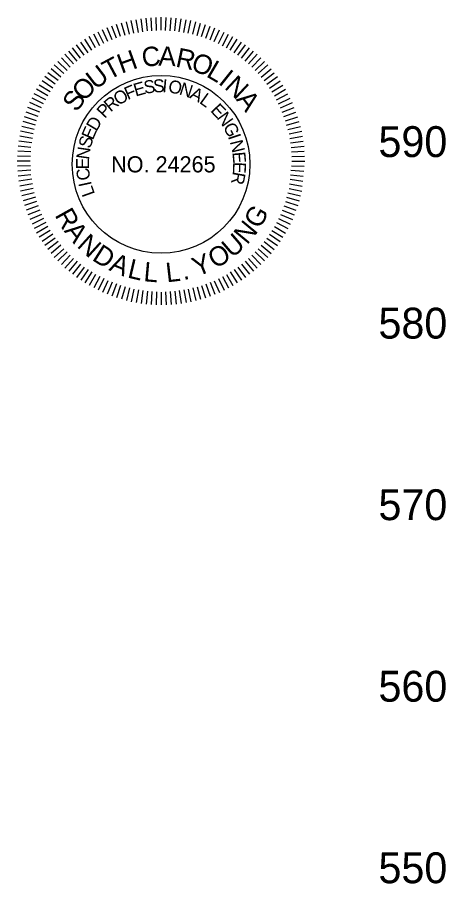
# Model space of a CAD drawing. Extents: x 1964377 to 1966966, y 1116414 to 1123213.
# Drawn here: x 1966831.8 to 1966949.9, y 1116676.7 to 1116915.3 of the extents above; entities that cross this region are included whole.
import ezdxf

# ---------------------------------------------------------------- set-up
doc = ezdxf.new("R2010")
doc.units = 0
doc.layers.add('RD_DDB_Profile_Elev', color=7, linetype='Continuous')
doc.layers.add('RD_TX_PEShield', color=7, linetype='Continuous')

msp = doc.modelspace()

# ---------------------------------------------------------------- linework, layer by layer
at = {"layer": 'RD_TX_PEShield'}
for p, q in [((1966861.52, 1116910.28), (1966860.54, 1116913.7)), ((1966861.52, 1116910.28), (1966860.54, 1116913.7)), ((1966862.74, 1116910.61), (1966861.88, 1116914.06)), ((1966862.74, 1116910.61), (1966861.88, 1116914.06)), ((1966863.95, 1116910.93), (1966863.21, 1116914.41)), ((1966863.95, 1116910.93), (1966863.21, 1116914.41)), ((1966865.2, 1116911.13), (1966864.58, 1116914.63)), ((1966865.2, 1116911.13), (1966864.58, 1116914.63)), ((1966866.44, 1116911.33), (1966865.94, 1116914.85)), ((1966866.44, 1116911.33), (1966865.94, 1116914.85)), ((1966867.68, 1116911.52), (1966867.31, 1116915.06)), ((1966867.68, 1116911.52), (1966867.31, 1116915.06)), ((1966868.94, 1116911.59), (1966868.69, 1116915.14)), ((1966868.94, 1116911.59), (1966868.69, 1116915.14)), ((1966870.19, 1116911.65), (1966870.07, 1116915.21)), ((1966870.19, 1116911.65), (1966870.07, 1116915.21)), ((1966871.45, 1116911.72), (1966871.45, 1116915.28)), ((1966871.45, 1116911.72), (1966871.45, 1116915.28)), ((1966872.7, 1116911.65), (1966872.83, 1116915.21)), ((1966872.7, 1116911.65), (1966872.83, 1116915.21)), ((1966873.96, 1116911.59), (1966874.21, 1116915.14)), ((1966873.96, 1116911.59), (1966874.21, 1116915.14)), ((1966875.21, 1116911.52), (1966875.59, 1116915.06)), ((1966875.21, 1116911.52), (1966875.59, 1116915.06)), ((1966876.46, 1116911.33), (1966876.95, 1116914.85)), ((1966876.46, 1116911.33), (1966876.95, 1116914.85)), ((1966877.7, 1116911.13), (1966878.32, 1116914.63)), ((1966877.7, 1116911.13), (1966878.32, 1116914.63)), ((1966878.94, 1116910.93), (1966879.68, 1116914.41)), ((1966878.94, 1116910.93), (1966879.68, 1116914.41)), ((1966878.94, 1116910.93), (1966879.68, 1116914.41)), ((1966880.16, 1116910.61), (1966881.02, 1116914.06)), ((1966880.16, 1116910.61), (1966881.02, 1116914.06)), ((1966880.16, 1116910.61), (1966881.02, 1116914.06)), ((1966881.37, 1116910.28), (1966882.35, 1116913.7)), ((1966881.37, 1116910.28), (1966882.35, 1116913.7)), ((1966881.37, 1116910.28), (1966882.35, 1116913.7)), ((1966855.66, 1116908.03), (1966854.11, 1116911.23)), ((1966855.66, 1116908.03), (1966854.11, 1116911.23)), ((1966856.79, 1116908.6), (1966855.34, 1116911.86)), ((1966856.79, 1116908.6), (1966855.34, 1116911.86)), ((1966857.96, 1116909.06), (1966856.63, 1116912.35)), ((1966857.96, 1116909.06), (1966856.63, 1116912.35)), ((1966859.13, 1116909.51), (1966857.92, 1116912.85)), ((1966859.13, 1116909.51), (1966857.92, 1116912.85)), ((1966860.31, 1116909.96), (1966859.21, 1116913.34)), ((1966860.31, 1116909.96), (1966859.21, 1116913.34)), ((1966882.59, 1116909.96), (1966883.69, 1116913.34)), ((1966882.59, 1116909.96), (1966883.69, 1116913.34)), ((1966882.59, 1116909.96), (1966883.69, 1116913.34)), ((1966883.76, 1116909.51), (1966884.98, 1116912.85)), ((1966883.76, 1116909.51), (1966884.98, 1116912.85)), ((1966883.76, 1116909.51), (1966884.98, 1116912.85)), ((1966884.93, 1116909.06), (1966886.26, 1116912.35)), ((1966884.93, 1116909.06), (1966886.26, 1116912.35)), ((1966884.93, 1116909.06), (1966886.26, 1116912.35)), ((1966886.11, 1116908.6), (1966887.56, 1116911.86)), ((1966886.11, 1116908.6), (1966887.56, 1116911.86)), ((1966886.11, 1116908.6), (1966887.56, 1116911.86)), ((1966887.23, 1116908.03), (1966888.79, 1116911.23)), ((1966887.23, 1116908.03), (1966888.79, 1116911.23)), ((1966887.23, 1116908.03), (1966888.79, 1116911.23)), ((1966852.37, 1116906.21), (1966850.48, 1116909.22)), ((1966852.37, 1116906.21), (1966850.48, 1116909.22)), ((1966853.42, 1116906.89), (1966851.64, 1116909.97)), ((1966853.42, 1116906.89), (1966851.64, 1116909.97)), ((1966854.55, 1116907.46), (1966852.88, 1116910.6)), ((1966854.55, 1116907.46), (1966852.88, 1116910.6)), ((1966888.35, 1116907.46), (1966890.02, 1116910.6)), ((1966888.35, 1116907.46), (1966890.02, 1116910.6)), ((1966888.35, 1116907.46), (1966890.02, 1116910.6)), ((1966889.47, 1116906.89), (1966891.25, 1116909.97)), ((1966889.47, 1116906.89), (1966891.25, 1116909.97)), ((1966889.47, 1116906.89), (1966891.25, 1116909.97)), ((1966890.52, 1116906.21), (1966892.41, 1116909.22)), ((1966890.52, 1116906.21), (1966892.41, 1116909.22)), ((1966890.52, 1116906.21), (1966892.41, 1116909.22)), ((1966849.28, 1116904.04), (1966847.09, 1116906.85)), ((1966849.28, 1116904.04), (1966847.09, 1116906.85)), ((1966850.26, 1116904.84), (1966848.17, 1116907.72)), ((1966850.26, 1116904.84), (1966848.17, 1116907.72)), ((1966851.32, 1116905.52), (1966849.33, 1116908.47)), ((1966851.32, 1116905.52), (1966849.33, 1116908.47)), ((1966891.58, 1116905.52), (1966893.57, 1116908.47)), ((1966891.58, 1116905.52), (1966893.57, 1116908.47)), ((1966891.58, 1116905.52), (1966893.57, 1116908.47)), ((1966892.63, 1116904.84), (1966894.73, 1116907.72)), ((1966892.63, 1116904.84), (1966894.73, 1116907.72)), ((1966892.63, 1116904.84), (1966894.73, 1116907.72)), ((1966893.61, 1116904.04), (1966895.8, 1116906.85)), ((1966893.61, 1116904.04), (1966895.8, 1116906.85)), ((1966893.61, 1116904.04), (1966895.8, 1116906.85)), ((1966846.44, 1116901.57), (1966843.97, 1116904.13)), ((1966846.44, 1116901.57), (1966843.97, 1116904.13)), ((1966847.33, 1116902.46), (1966844.95, 1116905.11)), ((1966847.33, 1116902.46), (1966844.95, 1116905.11)), ((1966848.31, 1116903.25), (1966846.02, 1116905.98)), ((1966848.31, 1116903.25), (1966846.02, 1116905.98)), ((1966894.59, 1116903.25), (1966896.87, 1116905.98)), ((1966894.59, 1116903.25), (1966896.87, 1116905.98)), ((1966894.59, 1116903.25), (1966896.87, 1116905.98)), ((1966895.57, 1116902.46), (1966897.95, 1116905.11)), ((1966895.57, 1116902.46), (1966897.95, 1116905.11)), ((1966895.57, 1116902.46), (1966897.95, 1116905.11)), ((1966896.46, 1116901.57), (1966898.93, 1116904.13)), ((1966896.46, 1116901.57), (1966898.93, 1116904.13)), ((1966896.46, 1116901.57), (1966898.93, 1116904.13)), ((1966844.66, 1116899.79), (1966842.01, 1116902.18)), ((1966844.66, 1116899.79), (1966842.01, 1116902.18)), ((1966845.55, 1116900.68), (1966842.99, 1116903.15)), ((1966845.55, 1116900.68), (1966842.99, 1116903.15)), ((1966897.34, 1116900.68), (1966899.9, 1116903.15)), ((1966897.34, 1116900.68), (1966899.9, 1116903.15)), ((1966897.34, 1116900.68), (1966899.9, 1116903.15)), ((1966898.23, 1116899.79), (1966900.88, 1116902.18)), ((1966898.23, 1116899.79), (1966900.88, 1116902.18)), ((1966898.23, 1116899.79), (1966900.88, 1116902.18)), ((1966843.08, 1116897.84), (1966840.28, 1116900.03)), ((1966843.08, 1116897.84), (1966840.28, 1116900.03)), ((1966843.87, 1116898.82), (1966841.14, 1116901.1)), ((1966843.87, 1116898.82), (1966841.14, 1116901.1)), ((1966899.03, 1116898.82), (1966901.75, 1116901.1)), ((1966899.03, 1116898.82), (1966901.75, 1116901.1)), ((1966899.03, 1116898.82), (1966901.75, 1116901.1)), ((1966899.82, 1116897.84), (1966902.62, 1116900.03)), ((1966899.82, 1116897.84), (1966902.62, 1116900.03)), ((1966899.82, 1116897.84), (1966902.62, 1116900.03)), ((1966841.6, 1116895.81), (1966838.65, 1116897.8)), ((1966841.6, 1116895.81), (1966838.65, 1116897.8)), ((1966842.29, 1116896.86), (1966839.41, 1116898.95)), ((1966842.29, 1116896.86), (1966839.41, 1116898.95)), ((1966900.61, 1116896.86), (1966903.49, 1116898.95)), ((1966900.61, 1116896.86), (1966903.49, 1116898.95)), ((1966900.61, 1116896.86), (1966903.49, 1116898.95)), ((1966901.29, 1116895.81), (1966904.24, 1116897.8)), ((1966901.29, 1116895.81), (1966904.24, 1116897.8)), ((1966901.29, 1116895.81), (1966904.24, 1116897.8)), ((1966840.23, 1116893.7), (1966837.15, 1116895.48)), ((1966840.23, 1116893.7), (1966837.15, 1116895.48)), ((1966840.92, 1116894.75), (1966837.9, 1116896.64)), ((1966840.92, 1116894.75), (1966837.9, 1116896.64)), ((1966901.98, 1116894.75), (1966904.99, 1116896.64)), ((1966901.98, 1116894.75), (1966904.99, 1116896.64)), ((1966901.98, 1116894.75), (1966904.99, 1116896.64)), ((1966902.66, 1116893.7), (1966905.75, 1116895.48)), ((1966902.66, 1116893.7), (1966905.75, 1116895.48)), ((1966902.66, 1116893.7), (1966905.75, 1116895.48)), ((1966839.09, 1116891.46), (1966835.89, 1116893.02)), ((1966839.09, 1116891.46), (1966835.89, 1116893.02)), ((1966839.66, 1116892.58), (1966836.52, 1116894.25)), ((1966839.66, 1116892.58), (1966836.52, 1116894.25)), ((1966903.23, 1116892.58), (1966906.37, 1116894.25)), ((1966903.23, 1116892.58), (1966906.37, 1116894.25)), ((1966903.23, 1116892.58), (1966906.37, 1116894.25)), ((1966903.8, 1116891.46), (1966907, 1116893.02)), ((1966903.8, 1116891.46), (1966907, 1116893.02)), ((1966903.8, 1116891.46), (1966907, 1116893.02)), ((1966838.07, 1116889.16), (1966834.77, 1116890.49)), ((1966838.07, 1116889.16), (1966834.77, 1116890.49)), ((1966838.52, 1116890.34), (1966835.27, 1116891.78)), ((1966838.52, 1116890.34), (1966835.27, 1116891.78)), ((1966904.38, 1116890.34), (1966907.63, 1116891.78)), ((1966904.38, 1116890.34), (1966907.63, 1116891.78)), ((1966904.38, 1116890.34), (1966907.63, 1116891.78)), ((1966904.83, 1116889.16), (1966908.12, 1116890.49)), ((1966904.83, 1116889.16), (1966908.12, 1116890.49)), ((1966904.83, 1116889.16), (1966908.12, 1116890.49)), ((1966837.17, 1116886.81), (1966833.78, 1116887.91)), ((1966837.17, 1116886.81), (1966833.78, 1116887.91)), ((1966837.62, 1116887.99), (1966834.28, 1116889.2)), ((1966837.62, 1116887.99), (1966834.28, 1116889.2)), ((1966905.28, 1116887.99), (1966908.62, 1116889.2)), ((1966905.28, 1116887.99), (1966908.62, 1116889.2)), ((1966905.28, 1116887.99), (1966908.62, 1116889.2)), ((1966905.73, 1116886.81), (1966909.11, 1116887.91)), ((1966905.73, 1116886.81), (1966909.11, 1116887.91)), ((1966905.73, 1116886.81), (1966909.11, 1116887.91)), ((1966836.52, 1116884.38), (1966833.07, 1116885.25)), ((1966836.52, 1116884.38), (1966833.07, 1116885.25)), ((1966836.84, 1116885.6), (1966833.42, 1116886.58)), ((1966836.84, 1116885.6), (1966833.42, 1116886.58)), ((1966906.05, 1116885.6), (1966909.47, 1116886.58)), ((1966906.05, 1116885.6), (1966909.47, 1116886.58)), ((1966906.05, 1116885.6), (1966909.47, 1116886.58)), ((1966906.38, 1116884.38), (1966909.83, 1116885.25)), ((1966906.38, 1116884.38), (1966909.83, 1116885.25)), ((1966906.38, 1116884.38), (1966909.83, 1116885.25)), ((1966836.19, 1116883.17), (1966832.71, 1116883.91)), ((1966836.19, 1116883.17), (1966832.71, 1116883.91)), ((1966906.7, 1116883.17), (1966910.19, 1116883.91)), ((1966906.7, 1116883.17), (1966910.19, 1116883.91)), ((1966906.7, 1116883.17), (1966910.19, 1116883.91)), ((1966835.8, 1116880.69), (1966832.27, 1116881.18)), ((1966835.8, 1116880.69), (1966832.27, 1116881.18)), ((1966835.99, 1116881.93), (1966832.49, 1116882.54)), ((1966835.99, 1116881.93), (1966832.49, 1116882.54)), ((1966906.9, 1116881.93), (1966910.4, 1116882.54)), ((1966906.9, 1116881.93), (1966910.4, 1116882.54)), ((1966906.9, 1116881.93), (1966910.4, 1116882.54)), ((1966907.1, 1116880.69), (1966910.62, 1116881.18)), ((1966907.1, 1116880.69), (1966910.62, 1116881.18)), ((1966907.1, 1116880.69), (1966910.62, 1116881.18)), ((1966835.53, 1116878.19), (1966831.99, 1116878.43)), ((1966835.53, 1116878.19), (1966831.99, 1116878.43)), ((1966835.6, 1116879.44), (1966832.06, 1116879.82)), ((1966835.6, 1116879.44), (1966832.06, 1116879.82)), ((1966907.29, 1116879.44), (1966910.83, 1116879.82)), ((1966907.29, 1116879.44), (1966910.83, 1116879.82)), ((1966907.29, 1116879.44), (1966910.83, 1116879.82)), ((1966907.36, 1116878.19), (1966910.91, 1116878.43)), ((1966907.36, 1116878.19), (1966910.91, 1116878.43)), ((1966907.36, 1116878.19), (1966910.91, 1116878.43)), ((1966835.4, 1116875.68), (1966831.84, 1116875.68)), ((1966835.4, 1116875.68), (1966831.84, 1116875.68)), ((1966835.47, 1116876.93), (1966831.91, 1116877.06)), ((1966835.47, 1116876.93), (1966831.91, 1116877.06)), ((1966907.43, 1116876.93), (1966910.98, 1116877.06)), ((1966907.43, 1116876.93), (1966910.98, 1116877.06)), ((1966907.43, 1116876.93), (1966910.98, 1116877.06)), ((1966907.49, 1116875.68), (1966911.05, 1116875.68)), ((1966907.49, 1116875.68), (1966911.05, 1116875.68)), ((1966907.49, 1116875.68), (1966911.05, 1116875.68)), ((1966835.47, 1116874.42), (1966831.91, 1116874.29)), ((1966835.47, 1116874.42), (1966831.91, 1116874.29)), ((1966835.53, 1116873.16), (1966831.99, 1116872.92)), ((1966835.53, 1116873.16), (1966831.99, 1116872.92)), ((1966907.23, 1116873.17), (1966910.76, 1116872.93)), ((1966907.23, 1116873.17), (1966910.76, 1116872.93)), ((1966907.36, 1116874.42), (1966910.91, 1116874.3)), ((1966907.36, 1116874.42), (1966910.91, 1116874.3)), ((1966835.6, 1116871.91), (1966832.06, 1116871.54)), ((1966835.6, 1116871.91), (1966832.06, 1116871.54)), ((1966835.8, 1116870.67), (1966832.27, 1116870.17)), ((1966835.8, 1116870.67), (1966832.27, 1116870.17)), ((1966906.97, 1116870.68), (1966910.48, 1116870.19)), ((1966906.97, 1116870.68), (1966910.48, 1116870.19)), ((1966907.1, 1116871.93), (1966910.62, 1116871.56)), ((1966907.1, 1116871.93), (1966910.62, 1116871.56)), ((1966835.99, 1116869.42), (1966832.49, 1116868.81)), ((1966835.99, 1116869.42), (1966832.49, 1116868.81)), ((1966906.84, 1116869.44), (1966910.33, 1116868.82)), ((1966906.84, 1116869.44), (1966910.33, 1116868.82)), ((1966836.19, 1116868.18), (1966832.71, 1116867.44)), ((1966836.19, 1116868.18), (1966832.71, 1116867.44)), ((1966836.52, 1116866.97), (1966833.07, 1116866.11)), ((1966836.52, 1116866.97), (1966833.07, 1116866.11)), ((1966906.38, 1116866.97), (1966909.83, 1116866.11)), ((1966906.38, 1116866.97), (1966909.83, 1116866.11)), ((1966906.7, 1116868.18), (1966910.19, 1116867.44)), ((1966906.7, 1116868.18), (1966910.19, 1116867.44)), ((1966836.84, 1116865.75), (1966833.42, 1116864.77)), ((1966836.84, 1116865.75), (1966833.42, 1116864.77)), ((1966837.17, 1116864.54), (1966833.78, 1116863.44)), ((1966905.73, 1116864.54), (1966909.11, 1116863.44)), ((1966905.73, 1116864.54), (1966909.11, 1116863.44)), ((1966906.05, 1116865.75), (1966909.47, 1116864.77)), ((1966906.05, 1116865.75), (1966909.47, 1116864.77)), ((1966837.62, 1116863.36), (1966834.28, 1116862.15)), ((1966837.62, 1116863.36), (1966834.28, 1116862.15)), ((1966838.07, 1116862.19), (1966834.77, 1116860.86)), ((1966838.07, 1116862.19), (1966834.77, 1116860.86)), ((1966904.83, 1116862.19), (1966908.12, 1116860.86)), ((1966904.83, 1116862.19), (1966908.12, 1116860.86)), ((1966905.28, 1116863.36), (1966908.62, 1116862.15)), ((1966905.28, 1116863.36), (1966908.62, 1116862.15)), ((1966838.52, 1116861.01), (1966835.27, 1116859.57)), ((1966838.52, 1116861.01), (1966835.27, 1116859.57)), ((1966839.09, 1116859.89), (1966835.89, 1116858.33)), ((1966839.09, 1116859.89), (1966835.89, 1116858.33)), ((1966839.66, 1116858.77), (1966836.52, 1116857.1)), ((1966839.66, 1116858.77), (1966836.52, 1116857.1)), ((1966903.23, 1116858.77), (1966906.37, 1116857.1)), ((1966903.23, 1116858.77), (1966906.37, 1116857.1)), ((1966903.8, 1116859.89), (1966907, 1116858.33)), ((1966903.8, 1116859.89), (1966907, 1116858.33)), ((1966904.38, 1116861.01), (1966907.63, 1116859.57)), ((1966904.38, 1116861.01), (1966907.63, 1116859.57)), ((1966840.23, 1116857.65), (1966837.15, 1116855.87)), ((1966840.23, 1116857.65), (1966837.15, 1116855.87)), ((1966840.92, 1116856.6), (1966837.9, 1116854.71)), ((1966840.92, 1116856.6), (1966837.9, 1116854.71)), ((1966901.98, 1116856.6), (1966904.99, 1116854.71)), ((1966901.98, 1116856.6), (1966904.99, 1116854.71)), ((1966902.66, 1116857.65), (1966905.75, 1116855.87)), ((1966902.66, 1116857.65), (1966905.75, 1116855.87)), ((1966841.6, 1116855.54), (1966838.65, 1116853.56)), ((1966841.6, 1116855.54), (1966838.65, 1116853.56)), ((1966842.29, 1116854.49), (1966839.41, 1116852.4)), ((1966842.29, 1116854.49), (1966839.41, 1116852.4)), ((1966900.61, 1116854.49), (1966903.49, 1116852.4)), ((1966900.61, 1116854.49), (1966903.49, 1116852.4)), ((1966901.29, 1116855.54), (1966904.24, 1116853.56)), ((1966901.29, 1116855.54), (1966904.24, 1116853.56)), ((1966843.08, 1116853.51), (1966840.28, 1116851.32)), ((1966843.08, 1116853.51), (1966840.28, 1116851.32)), ((1966843.87, 1116852.53), (1966841.14, 1116850.25)), ((1966843.87, 1116852.53), (1966841.14, 1116850.25)), ((1966844.66, 1116851.56), (1966842.01, 1116849.17)), ((1966844.66, 1116851.56), (1966842.01, 1116849.17)), ((1966898.23, 1116851.56), (1966900.88, 1116849.17)), ((1966898.23, 1116851.56), (1966900.88, 1116849.17)), ((1966899.03, 1116852.53), (1966901.75, 1116850.25)), ((1966899.03, 1116852.53), (1966901.75, 1116850.25)), ((1966899.82, 1116853.51), (1966902.62, 1116851.32)), ((1966899.82, 1116853.51), (1966902.62, 1116851.32)), ((1966845.55, 1116850.67), (1966842.99, 1116848.2)), ((1966845.55, 1116850.67), (1966842.99, 1116848.2)), ((1966846.44, 1116849.78), (1966843.97, 1116847.22)), ((1966846.44, 1116849.78), (1966843.97, 1116847.22)), ((1966896.46, 1116849.78), (1966898.93, 1116847.22)), ((1966896.46, 1116849.78), (1966898.93, 1116847.22)), ((1966897.34, 1116850.67), (1966899.9, 1116848.2)), ((1966897.34, 1116850.67), (1966899.9, 1116848.2)), ((1966847.33, 1116848.89), (1966844.95, 1116846.24)), ((1966847.33, 1116848.89), (1966844.95, 1116846.24)), ((1966848.31, 1116848.1), (1966846.02, 1116845.37)), ((1966848.31, 1116848.1), (1966846.02, 1116845.37)), ((1966849.28, 1116847.31), (1966847.09, 1116844.5)), ((1966849.28, 1116847.31), (1966847.09, 1116844.5)), ((1966893.61, 1116847.31), (1966895.8, 1116844.5)), ((1966893.61, 1116847.31), (1966895.8, 1116844.5)), ((1966894.59, 1116848.1), (1966896.87, 1116845.37)), ((1966894.59, 1116848.1), (1966896.87, 1116845.37)), ((1966895.57, 1116848.89), (1966897.95, 1116846.24)), ((1966850.26, 1116846.51), (1966848.17, 1116843.63)), ((1966850.26, 1116846.51), (1966848.17, 1116843.63)), ((1966851.32, 1116845.83), (1966849.33, 1116842.88)), ((1966851.32, 1116845.83), (1966849.33, 1116842.88)), ((1966852.37, 1116845.14), (1966850.48, 1116842.13)), ((1966852.37, 1116845.14), (1966850.48, 1116842.13)), ((1966853.42, 1116844.46), (1966851.64, 1116841.38)), ((1966853.42, 1116844.46), (1966851.64, 1116841.38)), ((1966889.47, 1116844.46), (1966891.25, 1116841.38)), ((1966889.47, 1116844.46), (1966891.25, 1116841.38)), ((1966890.52, 1116845.14), (1966892.41, 1116842.13)), ((1966890.52, 1116845.14), (1966892.41, 1116842.13)), ((1966891.58, 1116845.83), (1966893.57, 1116842.88)), ((1966891.58, 1116845.83), (1966893.57, 1116842.88)), ((1966892.63, 1116846.51), (1966894.73, 1116843.63)), ((1966892.63, 1116846.51), (1966894.73, 1116843.63)), ((1966854.55, 1116843.89), (1966852.88, 1116840.75)), ((1966854.55, 1116843.89), (1966852.88, 1116840.75)), ((1966855.66, 1116843.32), (1966854.11, 1116840.12)), ((1966855.66, 1116843.32), (1966854.11, 1116840.12)), ((1966856.79, 1116842.75), (1966855.34, 1116839.49)), ((1966856.79, 1116842.75), (1966855.34, 1116839.49)), ((1966857.96, 1116842.3), (1966856.63, 1116839)), ((1966857.96, 1116842.3), (1966856.63, 1116839)), ((1966884.93, 1116842.3), (1966886.26, 1116839)), ((1966884.93, 1116842.3), (1966886.26, 1116839)), ((1966886.11, 1116842.75), (1966887.56, 1116839.49)), ((1966886.11, 1116842.75), (1966887.56, 1116839.49)), ((1966887.23, 1116843.32), (1966888.79, 1116840.12)), ((1966887.23, 1116843.32), (1966888.79, 1116840.12)), ((1966888.35, 1116843.89), (1966890.02, 1116840.75)), ((1966888.35, 1116843.89), (1966890.02, 1116840.75)), ((1966859.13, 1116841.85), (1966857.92, 1116838.5)), ((1966859.13, 1116841.85), (1966857.92, 1116838.5)), ((1966860.31, 1116841.39), (1966859.21, 1116838.01)), ((1966860.31, 1116841.39), (1966859.21, 1116838.01)), ((1966861.52, 1116841.07), (1966860.54, 1116837.65)), ((1966861.52, 1116841.07), (1966860.54, 1116837.65)), ((1966862.74, 1116840.74), (1966861.88, 1116837.29)), ((1966862.74, 1116840.74), (1966861.88, 1116837.29)), ((1966863.95, 1116840.42), (1966863.21, 1116836.94)), ((1966863.95, 1116840.42), (1966863.21, 1116836.94)), ((1966865.2, 1116840.22), (1966864.58, 1116836.72)), ((1966865.2, 1116840.22), (1966864.58, 1116836.72)), ((1966866.44, 1116840.02), (1966865.94, 1116836.5)), ((1966866.44, 1116840.02), (1966865.94, 1116836.5)), ((1966867.68, 1116839.83), (1966867.31, 1116836.29)), ((1966867.68, 1116839.83), (1966867.31, 1116836.29)), ((1966868.94, 1116839.76), (1966868.69, 1116836.22)), ((1966868.94, 1116839.76), (1966868.69, 1116836.22)), ((1966870.19, 1116839.7), (1966870.07, 1116836.14)), ((1966870.19, 1116839.7), (1966870.07, 1116836.14)), ((1966871.45, 1116839.63), (1966871.45, 1116836.07)), ((1966871.45, 1116839.63), (1966871.45, 1116836.07)), ((1966872.7, 1116839.7), (1966872.83, 1116836.14)), ((1966872.7, 1116839.7), (1966872.83, 1116836.14)), ((1966873.96, 1116839.76), (1966874.21, 1116836.22)), ((1966873.96, 1116839.76), (1966874.21, 1116836.22)), ((1966875.21, 1116839.83), (1966875.59, 1116836.29)), ((1966875.21, 1116839.83), (1966875.59, 1116836.29)), ((1966876.46, 1116840.02), (1966876.95, 1116836.5)), ((1966876.46, 1116840.02), (1966876.95, 1116836.5)), ((1966877.7, 1116840.22), (1966878.32, 1116836.72)), ((1966877.7, 1116840.22), (1966878.32, 1116836.72)), ((1966878.94, 1116840.42), (1966879.68, 1116836.94)), ((1966878.94, 1116840.42), (1966879.68, 1116836.94)), ((1966880.16, 1116840.74), (1966881.02, 1116837.29)), ((1966880.16, 1116840.74), (1966881.02, 1116837.29)), ((1966881.37, 1116841.07), (1966882.35, 1116837.65)), ((1966881.37, 1116841.07), (1966882.35, 1116837.65)), ((1966882.59, 1116841.39), (1966883.69, 1116838.01)), ((1966882.59, 1116841.39), (1966883.69, 1116838.01)), ((1966883.76, 1116841.85), (1966884.98, 1116838.5)), ((1966883.76, 1116841.85), (1966884.98, 1116838.5))]:
    msp.add_line(p, q, dxfattribs=at)
msp.add_circle((1966871.45, 1116874.8), 24.48, dxfattribs=at)

# ---------------------------------------------------------------- texts
at = {"layer": 'RD_DDB_Profile_Elev'}
for s, p in [('590', (1966931.34, 1116876.8)), ('580', (1966931.34, 1116826.8)), ('570', (1966931.34, 1116776.8)), ('560', (1966931.34, 1116726.8)), ('550', (1966931.34, 1116676.8))]:
    msp.add_text(s, height=8.5, dxfattribs=at).set_placement(p)
at = {"layer": 'RD_TX_PEShield'}
for s, height, rotation, p in [('C', 5.34, 6.8832, (1966866.44, 1116901.54)), ('A', 5.34, 357.9448, (1966870.66, 1116901.99)), ('R', 5.34, 348.267, (1966875.24, 1116901.73)), ('T', 5.34, 28.0947, (1966857.11, 1116897.91)), ('H', 5.34, 19.9102, (1966860.54, 1116899.72)), ('O', 5.34, 339.3286, (1966879.38, 1116900.82)), ('U', 5.34, 37.7726, (1966853.42, 1116895.17)), ('L', 5.34, 329.6507, (1966883.64, 1116899.11)), ('I', 5.34, 321.4663, (1966886.98, 1116897.13)), ('N', 5.34, 317.0007, (1966888.67, 1116895.85)), ('O', 5.34, 47.4504, (1966850.26, 1116891.85)), ('E', 3.56, 16.1843, (1966864.44, 1116893.43)), ('S', 3.56, 8.6909, (1966866.93, 1116894.19)), ('S', 3.56, 1.79, (1966869.3, 1116894.59)), ('I', 3.56, 354.889, (1966871.69, 1116894.7)), ('O', 3.56, 350.4045, (1966873.25, 1116894.62)), ('N', 3.56, 341.7029, (1966876.22, 1116894.12)), ('S', 5.34, 54.9027, (1966848.22, 1116888.96)), ('O', 3.56, 31.7869, (1966859.69, 1116890.86)), ('F', 3.56, 23.0853, (1966862.26, 1116892.46)), ('A', 3.56, 333.0013, (1966879.09, 1116893.18)), ('R', 3.56, 39.8902, (1966857.54, 1116889.04)), ('L', 3.56, 324.2997, (1966881.79, 1116891.81)), ('A', 5.34, 307.3229, (1966891.96, 1116892.66)), ('P', 3.56, 46.7912, (1966855.93, 1116887.27)), ('E', 3.56, 313.2251, (1966884.86, 1116889.51)), ('D', 3.56, 59.074, (1966853.63, 1116883.68)), ('N', 3.56, 305.7317, (1966886.66, 1116887.63)), ('E', 3.56, 66.5674, (1966852.63, 1116881.29)), ('G', 3.56, 297.0301, (1966888.43, 1116885.18)), ('I', 3.56, 288.3285, (1966889.81, 1116882.49)), ('S', 3.56, 73.4683, (1966851.98, 1116878.98)), ('N', 3.56, 283.8441, (1966890.35, 1116881.03)), ('N', 3.56, 82.17, (1966851.58, 1116875.98)), ('E', 3.56, 275.1424, (1966891.08, 1116878.1)), ('E', 3.56, 89.6633, (1966851.59, 1116873.38)), ('C', 3.56, 97.7667, (1966851.99, 1116870.6)), ('E', 3.56, 267.6491, (1966891.34, 1116875.51)), ('R', 3.56, 260.1557, (1966891.26, 1116872.91)), ('I', 3.56, 102.2511, (1966852.38, 1116869.09)), ('L', 3.56, 109.7445, (1966853.28, 1116866.65)), ('R', 5.34, 299.1493, (1966842.04, 1116860.82)), ('G', 5.34, 60.1113, (1966898.56, 1116856.77)), ('N', 5.34, 50.4335, (1966895.14, 1116852.47)), ('A', 5.34, 308.0877, (1966844.57, 1116856.42)), ('N', 5.34, 317.7655, (1966848.04, 1116852.17)), ('U', 5.34, 40.7556, (1966891.05, 1116848.81)), ('D', 5.34, 327.4433, (1966852.18, 1116848.56)), ('O', 5.34, 31.0778, (1966886.4, 1116845.88)), ('A', 5.34, 337.1212, (1966856.87, 1116845.69)), ('Y', 5.34, 21.4, (1966881.33, 1116843.78)), ('L', 5.34, 346.799, (1966861.97, 1116843.65)), ('L', 5.34, 354.9835, (1966866.5, 1116842.62)), ('L', 5.34, 6.5171, (1966873.03, 1116842.28)), ('.', 5.34, 14.7016, (1966877.64, 1116842.84))]:
    msp.add_text(s, height=height, rotation=rotation, dxfattribs=at).set_placement(p)
msp.add_text('NO. 24265', height=4.45, dxfattribs=at).set_placement((1966857.69, 1116872.57))

doc.saveas('drawing.dxf')
